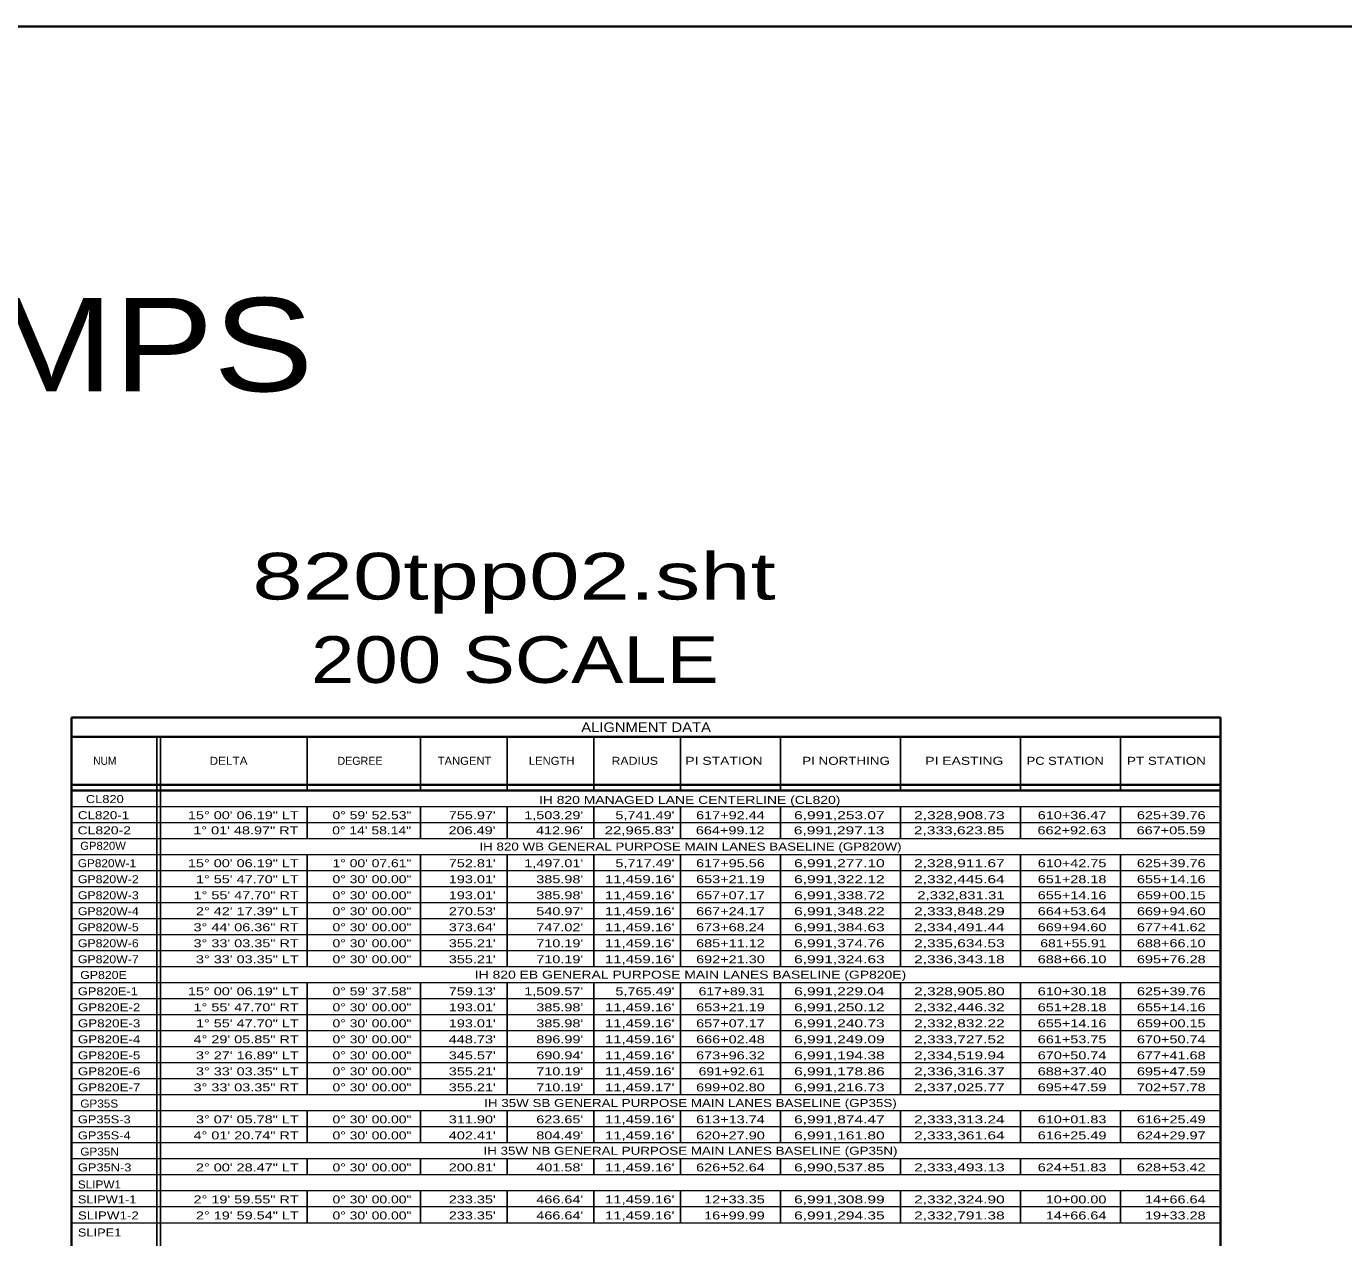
# Model space of a CAD drawing. Extents: x 1953053 to 1967065, y 7363860 to 7371201.
# Drawn here: x 1955866 to 1957841, y 7369385 to 7371201 of the extents above; entities that cross this region are included whole.
import ezdxf
from ezdxf.enums import TextEntityAlignment as Align

# ---------------------------------------------------------------- set-up
doc = ezdxf.new("R2010")
doc.units = 0
doc.header["$LTSCALE"] = 4.8
doc.layers.add('10', color=7, linetype='Continuous')
doc.layers.add('12', color=7, linetype='Continuous', lineweight=25)
doc.layers.add('62', color=7, linetype='Continuous', lineweight=35)

msp = doc.modelspace()

# ---------------------------------------------------------------- linework, layer by layer
at = {"layer": '12', "lineweight": 35}
for p, q in [((1957656.717, 7370164.879), (1955933.385, 7370164.879)), ((1955933.385, 7370164.879), (1955933.385, 7367607.746)), ((1957656.717, 7367607.746), (1957656.717, 7370164.879)), ((1955933.385, 7370136.079), (1957656.717, 7370136.079)), ((1955933.385, 7370064.079), (1957656.717, 7370064.079)), ((1955933.385, 7370055.746), (1957656.717, 7370055.746))]:
    msp.add_line(p, q, dxfattribs=at)
at = {"layer": '12'}
for p, q in [((1956061.23, 7370136.079), (1956061.23, 7367607.746)), ((1956066.717, 7370136.079), (1956066.717, 7367607.746)), ((1956286.717, 7370136.079), (1956286.717, 7370055.746)), ((1956456.717, 7370136.079), (1956456.717, 7370055.746)), ((1956586.717, 7370136.079), (1956586.717, 7370055.746)), ((1956716.717, 7370136.079), (1956716.717, 7370055.746)), ((1956846.717, 7370136.079), (1956846.717, 7370055.746)), ((1956996.717, 7370136.079), (1956996.717, 7370055.746)), ((1957176.717, 7370136.079), (1957176.717, 7370055.746)), ((1957356.717, 7370136.079), (1957356.717, 7370055.746)), ((1957506.717, 7370136.079), (1957506.717, 7370055.746)), ((1956061.23, 7370114.479), (1956061.23, 7369838.526)), ((1956286.717, 7370031.746), (1956286.717, 7369983.746)), ((1956456.717, 7370031.746), (1956456.717, 7369983.746)), ((1956586.717, 7370031.746), (1956586.717, 7369983.746)), ((1956716.717, 7370031.746), (1956716.717, 7369983.746)), ((1956846.717, 7370031.746), (1956846.717, 7369983.746)), ((1956996.717, 7370031.746), (1956996.717, 7369983.746)), ((1957176.717, 7370031.746), (1957176.717, 7369983.746)), ((1957356.717, 7370031.746), (1957356.717, 7369983.746)), ((1957506.717, 7370031.746), (1957506.717, 7369983.746)), ((1956286.717, 7369959.746), (1956286.717, 7369791.746)), ((1956456.717, 7369959.746), (1956456.717, 7369791.746)), ((1956586.717, 7369959.746), (1956586.717, 7369791.746)), ((1956716.717, 7369959.746), (1956716.717, 7369791.746)), ((1956846.717, 7369959.746), (1956846.717, 7369791.746)), ((1956996.717, 7369959.746), (1956996.717, 7369791.746)), ((1957176.717, 7369959.746), (1957176.717, 7369791.746)), ((1957356.717, 7369959.746), (1957356.717, 7369791.746)), ((1957506.717, 7369959.746), (1957506.717, 7369791.746)), ((1956286.717, 7369767.746), (1956286.717, 7369599.746)), ((1956456.717, 7369767.746), (1956456.717, 7369599.746)), ((1956586.717, 7369767.746), (1956586.717, 7369599.746)), ((1956716.717, 7369767.746), (1956716.717, 7369599.746)), ((1956846.717, 7369767.746), (1956846.717, 7369599.746)), ((1956996.717, 7369767.746), (1956996.717, 7369599.746)), ((1957176.717, 7369767.746), (1957176.717, 7369599.699)), ((1957356.717, 7369767.746), (1957356.717, 7369599.746)), ((1957506.717, 7369767.746), (1957506.717, 7369599.746)), ((1956286.717, 7369575.746), (1956286.717, 7369527.746)), ((1956456.717, 7369575.746), (1956456.717, 7369527.746)), ((1956586.717, 7369575.746), (1956586.717, 7369527.746)), ((1956716.717, 7369575.746), (1956716.717, 7369527.746)), ((1956846.717, 7369575.746), (1956846.717, 7369527.746)), ((1956996.717, 7369575.746), (1956996.717, 7369527.746)), ((1957176.717, 7369575.746), (1957176.717, 7369527.746)), ((1957356.717, 7369575.746), (1957356.717, 7369527.746)), ((1957506.717, 7369575.746), (1957506.717, 7369527.746)), ((1956286.717, 7369503.746), (1956286.717, 7369479.746)), ((1956456.717, 7369503.746), (1956456.717, 7369479.746)), ((1956586.717, 7369503.746), (1956586.717, 7369479.746)), ((1956716.717, 7369503.746), (1956716.717, 7369479.746)), ((1956846.717, 7369503.746), (1956846.717, 7369479.746)), ((1956996.717, 7369503.746), (1956996.717, 7369479.746)), ((1957176.717, 7369503.746), (1957176.717, 7369479.746)), ((1957356.717, 7369503.746), (1957356.717, 7369479.746)), ((1957506.717, 7369503.746), (1957506.717, 7369479.746)), ((1956286.717, 7369455.746), (1956286.717, 7369407.746)), ((1956456.717, 7369455.746), (1956456.717, 7369407.746)), ((1956586.717, 7369455.746), (1956586.717, 7369407.746)), ((1956716.717, 7369455.746), (1956716.717, 7369407.746)), ((1956846.717, 7369455.746), (1956846.717, 7369407.746)), ((1956996.717, 7369455.746), (1956996.717, 7369407.746)), ((1957176.717, 7369455.746), (1957176.717, 7369407.746)), ((1957356.717, 7369455.746), (1957356.717, 7369407.746)), ((1957506.717, 7369455.746), (1957506.717, 7369407.746))]:
    msp.add_line(p, q, dxfattribs=at)
at = {"layer": '12', "lineweight": 13}
for p, q in [((1955933.385, 7370031.746), (1957656.717, 7370031.746)), ((1955933.385, 7370007.746), (1957656.717, 7370007.746)), ((1955933.385, 7369983.746), (1957656.717, 7369983.746)), ((1955933.385, 7369959.746), (1957656.717, 7369959.746)), ((1955933.385, 7369935.746), (1957656.717, 7369935.746)), ((1955933.385, 7369911.746), (1957656.717, 7369911.746)), ((1955933.385, 7369887.746), (1957656.717, 7369887.746)), ((1955933.385, 7369863.746), (1957656.717, 7369863.746)), ((1955933.385, 7369839.746), (1957656.717, 7369839.746)), ((1955933.385, 7369815.746), (1957656.717, 7369815.746)), ((1955933.385, 7369791.746), (1957656.717, 7369791.746)), ((1955933.385, 7369767.746), (1957656.717, 7369767.746)), ((1955933.385, 7369743.746), (1957656.717, 7369743.746)), ((1955933.385, 7369719.746), (1957656.717, 7369719.746)), ((1955933.385, 7369695.746), (1957656.717, 7369695.746)), ((1955933.385, 7369671.746), (1957656.717, 7369671.746)), ((1955933.385, 7369647.746), (1957656.717, 7369647.746)), ((1955933.385, 7369623.746), (1957656.717, 7369623.746)), ((1955933.385, 7369599.746), (1957656.717, 7369599.746)), ((1955933.385, 7369575.746), (1957656.717, 7369575.746)), ((1955933.385, 7369551.746), (1957656.717, 7369551.746)), ((1955933.385, 7369527.746), (1957656.717, 7369527.746)), ((1955933.385, 7369503.746), (1957656.717, 7369503.746)), ((1955933.385, 7369479.746), (1957656.717, 7369479.746)), ((1955933.385, 7369455.746), (1957656.717, 7369455.746)), ((1955933.385, 7369431.746), (1957656.717, 7369431.746)), ((1955933.385, 7369407.746), (1957656.717, 7369407.746))]:
    msp.add_line(p, q, dxfattribs=at)
at = {"layer": '62'}
msp.add_lwpolyline([(1953052.784, 7371201.108), (1967065.314, 7371201.108), (1967065.314, 7363859.877), (1953052.784, 7363859.877)], close=True, dxfattribs=at)

# ---------------------------------------------------------------- texts
at = {"layer": '10'}
for s, width, p in [('CL820', 1.2, (1955955.056, 7370036.747)), ('CL820-1', 1.25, (1955943.006, 7370012.573)), ('CL820-2', 1.3, (1955942.614, 7369989.838)), ('GP820W', 1.05, (1955946.565, 7369966.718)), ('GP820W-1', 1.1, (1955943.006, 7369940.573)), ('GP820W-2', 1.15, (1955943.006, 7369916.573)), ('GP820W-3', 1.15, (1955943.006, 7369892.573)), ('GP820W-4', 1.15, (1955943.006, 7369868.573)), ('GP820W-5', 1.15, (1955943.006, 7369844.573)), ('GP820W-6', 1.15, (1955943.006, 7369820.573)), ('GP820W-7', 1.15, (1955943.006, 7369796.573)), ('GP820E', 1.15, (1955946.565, 7369773.083)), ('GP820E-1', 1.2, (1955943.006, 7369748.573)), ('GP820E-2', 1.25, (1955943.006, 7369724.573)), ('GP820E-3', 1.25, (1955943.006, 7369700.573)), ('GP820E-4', 1.25, (1955943.006, 7369676.573)), ('GP820E-5', 1.25, (1955943.006, 7369652.573)), ('GP820E-6', 1.25, (1955943.006, 7369628.573)), ('GP820E-7', 1.25, (1955943.006, 7369604.573)), ('GP35S', 1.1, (1955946.565, 7369580.275)), ('GP35S-3', 1.2, (1955943.006, 7369556.573)), ('GP35S-4', 1.2, (1955943.006, 7369532.573)), ('GP35N', 1.1, (1955946.565, 7369508.283)), ('GP35N-3', 1.2, (1955943.006, 7369484.573)), ('SLIPW1', 1.1, (1955943.006, 7369459.016)), ('SLIPW1-1', 1.2, (1955943.006, 7369436.573)), ('SLIPW1-2', 1.25, (1955943.006, 7369412.573)), ('SLIPE1', 1.2, (1955943.006, 7369387.016))]:
    msp.add_text(s, height=12, dxfattribs=dict(at, width=width)).set_placement(p)
for s, width, p in [('IH 820 MANAGED LANE CENTERLINE (CL820)', 1.3, (1956860.508, 7370035.509)), ('IH 820 WB GENERAL PURPOSE MAIN LANES BASELINE (GP820W)', 1.25, (1956861.718, 7369965.54)), ('IH 820 EB GENERAL PURPOSE MAIN LANES BASELINE (GP820E)', 1.3, (1956861.718, 7369773.54)), ('IH 35W SB GENERAL PURPOSE MAIN LANES BASELINE (GP35S)', 1.25, (1956861.717, 7369581.158)), ('IH 35W NB GENERAL PURPOSE MAIN LANES BASELINE (GP35N)', 1.25, (1956861.717, 7369509.54))]:
    msp.add_text(s, height=12, dxfattribs=dict(at, width=width)).set_placement(p, align=Align.CENTER)
for s, width, p in [('15° 00\' 06.19" LT', 1.35, (1956274.239, 7370012.573)), ('0° 59\' 52.53"', 1.3, (1956443.234, 7370012.573)), ("755.97'", 1.35, (1956569.644, 7370012.573)), ("1,503.29'", 1.35, (1956700.841, 7370012.573)), ("5,741.49'", 1.35, (1956837.61, 7370012.573)), ('617+92.44', 1.35, (1956973.154, 7370012.573)), ('6,991,253.07', 1.45, (1957152.919, 7370012.573)), ('2,328,908.73', 1.45, (1957332.919, 7370012.573)), ('610+36.47', 1.35, (1957485.497, 7370012.573)), ('625+39.76', 1.35, (1957634.229, 7370012.573)), ('1° 01\' 48.97" RT', 1.35, (1956273.847, 7369989.838)), ('0° 14\' 58.14"', 1.3, (1956442.842, 7369989.838)), ("206.49'", 1.35, (1956569.252, 7369989.838)), ("412.96'", 1.35, (1956700.449, 7369989.838)), ("22,965.83'", 1.4, (1956837.218, 7369989.838)), ('664+99.12', 1.35, (1956972.762, 7369989.838)), ('6,991,297.13', 1.45, (1957152.527, 7369989.838)), ('2,333,623.85', 1.45, (1957332.527, 7369989.838)), ('662+92.63', 1.35, (1957485.105, 7369989.838)), ('667+05.59', 1.35, (1957633.837, 7369989.838)), ('15° 00\' 06.19" LT', 1.35, (1956274.239, 7369940.573)), ('1° 00\' 07.61"', 1.3, (1956443.234, 7369940.573)), ("752.81'", 1.35, (1956569.644, 7369940.573)), ("1,497.01'", 1.35, (1956700.841, 7369940.573)), ("5,717.49'", 1.35, (1956837.61, 7369940.573)), ('617+95.56', 1.35, (1956973.154, 7369940.573)), ('6,991,277.10', 1.45, (1957152.919, 7369940.573)), ('2,328,911.67', 1.45, (1957332.919, 7369940.573)), ('610+42.75', 1.35, (1957485.497, 7369940.573)), ('625+39.76', 1.35, (1957634.229, 7369940.573)), ('1° 55\' 47.70" LT', 1.35, (1956274.239, 7369916.573)), ('0° 30\' 00.00"', 1.3, (1956443.234, 7369916.573)), ("193.01'", 1.35, (1956569.644, 7369916.573)), ("385.98'", 1.35, (1956700.841, 7369916.573)), ("11,459.16'", 1.4, (1956837.61, 7369916.573)), ('653+21.19', 1.35, (1956973.154, 7369916.573)), ('6,991,322.12', 1.45, (1957152.919, 7369916.573)), ('2,332,445.64', 1.45, (1957332.919, 7369916.573)), ('651+28.18', 1.35, (1957485.497, 7369916.573)), ('655+14.16', 1.35, (1957634.229, 7369916.573)), ('1° 55\' 47.70" RT', 1.35, (1956274.239, 7369892.573)), ('0° 30\' 00.00"', 1.3, (1956443.234, 7369892.573)), ("193.01'", 1.35, (1956569.644, 7369892.573)), ("385.98'", 1.35, (1956700.841, 7369892.573)), ("11,459.16'", 1.4, (1956837.61, 7369892.573)), ('657+07.17', 1.35, (1956973.154, 7369892.573)), ('6,991,338.72', 1.45, (1957152.919, 7369892.573)), ('2,332,831.31', 1.4, (1957332.919, 7369892.573)), ('655+14.16', 1.35, (1957485.497, 7369892.573)), ('659+00.15', 1.35, (1957634.229, 7369892.573)), ('2° 42\' 17.39" LT', 1.35, (1956274.239, 7369868.573)), ('0° 30\' 00.00"', 1.3, (1956443.234, 7369868.573)), ("270.53'", 1.35, (1956569.644, 7369868.573)), ("540.97'", 1.35, (1956700.841, 7369868.573)), ("11,459.16'", 1.4, (1956837.61, 7369868.573)), ('667+24.17', 1.35, (1956973.154, 7369868.573)), ('6,991,348.22', 1.45, (1957152.919, 7369868.573)), ('2,333,848.29', 1.45, (1957332.919, 7369868.573)), ('664+53.64', 1.35, (1957485.497, 7369868.573)), ('669+94.60', 1.35, (1957634.229, 7369868.573)), ('3° 44\' 06.36" RT', 1.35, (1956274.239, 7369844.573)), ('0° 30\' 00.00"', 1.3, (1956443.234, 7369844.573)), ("373.64'", 1.35, (1956569.644, 7369844.573)), ("747.02'", 1.35, (1956700.841, 7369844.573)), ("11,459.16'", 1.4, (1956837.61, 7369844.573)), ('673+68.24', 1.35, (1956973.154, 7369844.573)), ('6,991,384.63', 1.45, (1957152.919, 7369844.573)), ('2,334,491.44', 1.45, (1957332.919, 7369844.573)), ('669+94.60', 1.35, (1957485.497, 7369844.573)), ('677+41.62', 1.35, (1957634.229, 7369844.573)), ('3° 33\' 03.35" RT', 1.35, (1956274.239, 7369820.573)), ('0° 30\' 00.00"', 1.3, (1956443.234, 7369820.573)), ("355.21'", 1.35, (1956569.644, 7369820.573)), ("710.19'", 1.35, (1956700.841, 7369820.573)), ("11,459.16'", 1.4, (1956837.61, 7369820.573)), ('685+11.12', 1.35, (1956973.154, 7369820.573)), ('6,991,374.76', 1.45, (1957152.919, 7369820.573)), ('2,335,634.53', 1.45, (1957332.919, 7369820.573)), ('681+55.91', 1.3, (1957485.497, 7369820.573)), ('688+66.10', 1.35, (1957634.229, 7369820.573)), ('3° 33\' 03.35" LT', 1.35, (1956274.239, 7369796.573)), ('0° 30\' 00.00"', 1.3, (1956443.234, 7369796.573)), ("355.21'", 1.35, (1956569.644, 7369796.573)), ("710.19'", 1.35, (1956700.841, 7369796.573)), ("11,459.16'", 1.4, (1956837.61, 7369796.573)), ('692+21.30', 1.35, (1956973.154, 7369796.573)), ('6,991,324.63', 1.45, (1957152.919, 7369796.573)), ('2,336,343.18', 1.45, (1957332.919, 7369796.573)), ('688+66.10', 1.35, (1957485.497, 7369796.573)), ('695+76.28', 1.35, (1957634.229, 7369796.573)), ('15° 00\' 06.19" LT', 1.35, (1956274.239, 7369748.573)), ('0° 59\' 37.58"', 1.3, (1956443.234, 7369748.573)), ("759.13'", 1.35, (1956569.644, 7369748.573)), ("1,509.57'", 1.35, (1956700.841, 7369748.573)), ("5,765.49'", 1.35, (1956837.61, 7369748.573)), ('617+89.31', 1.3, (1956973.154, 7369748.573)), ('6,991,229.04', 1.45, (1957152.919, 7369748.573)), ('2,328,905.80', 1.45, (1957332.919, 7369748.573)), ('610+30.18', 1.35, (1957485.497, 7369748.573)), ('625+39.76', 1.35, (1957634.229, 7369748.573)), ('1° 55\' 47.70" RT', 1.35, (1956274.239, 7369724.573)), ('0° 30\' 00.00"', 1.3, (1956443.234, 7369724.573)), ("193.01'", 1.35, (1956569.644, 7369724.573)), ("385.98'", 1.35, (1956700.841, 7369724.573)), ("11,459.16'", 1.4, (1956837.61, 7369724.573)), ('653+21.19', 1.35, (1956973.154, 7369724.573)), ('6,991,250.12', 1.45, (1957152.919, 7369724.573)), ('2,332,446.32', 1.45, (1957332.919, 7369724.573)), ('651+28.18', 1.35, (1957485.497, 7369724.573)), ('655+14.16', 1.35, (1957634.229, 7369724.573)), ('1° 55\' 47.70" LT', 1.35, (1956274.239, 7369700.573)), ('0° 30\' 00.00"', 1.3, (1956443.234, 7369700.573)), ("193.01'", 1.35, (1956569.644, 7369700.573)), ("385.98'", 1.35, (1956700.841, 7369700.573)), ("11,459.16'", 1.4, (1956837.61, 7369700.573)), ('657+07.17', 1.35, (1956973.154, 7369700.573)), ('6,991,240.73', 1.45, (1957152.919, 7369700.573)), ('2,332,832.22', 1.45, (1957332.919, 7369700.573)), ('655+14.16', 1.35, (1957485.497, 7369700.573)), ('659+00.15', 1.35, (1957634.229, 7369700.573)), ('4° 29\' 05.85" RT', 1.35, (1956274.239, 7369676.573)), ('0° 30\' 00.00"', 1.3, (1956443.234, 7369676.573)), ("448.73'", 1.35, (1956569.644, 7369676.573)), ("896.99'", 1.35, (1956700.841, 7369676.573)), ("11,459.16'", 1.4, (1956837.61, 7369676.573)), ('666+02.48', 1.35, (1956973.154, 7369676.573)), ('6,991,249.09', 1.45, (1957152.919, 7369676.573)), ('2,333,727.52', 1.45, (1957332.919, 7369676.573)), ('661+53.75', 1.35, (1957485.497, 7369676.573)), ('670+50.74', 1.35, (1957634.229, 7369676.573)), ('3° 27\' 16.89" LT', 1.35, (1956274.239, 7369652.573)), ('0° 30\' 00.00"', 1.3, (1956443.234, 7369652.573)), ("345.57'", 1.35, (1956569.644, 7369652.573)), ("690.94'", 1.35, (1956700.841, 7369652.573)), ("11,459.16'", 1.4, (1956837.61, 7369652.573)), ('673+96.32', 1.35, (1956973.154, 7369652.573)), ('6,991,194.38', 1.45, (1957152.919, 7369652.573)), ('2,334,519.94', 1.45, (1957332.919, 7369652.573)), ('670+50.74', 1.35, (1957485.497, 7369652.573)), ('677+41.68', 1.35, (1957634.229, 7369652.573)), ('3° 33\' 03.35" LT', 1.35, (1956274.239, 7369628.573)), ('0° 30\' 00.00"', 1.3, (1956443.234, 7369628.573)), ("355.21'", 1.35, (1956569.644, 7369628.573)), ("710.19'", 1.35, (1956700.841, 7369628.573)), ("11,459.16'", 1.4, (1956837.61, 7369628.573)), ('691+92.61', 1.3, (1956973.154, 7369628.573)), ('6,991,178.86', 1.45, (1957152.919, 7369628.573)), ('2,336,316.37', 1.45, (1957332.919, 7369628.573)), ('688+37.40', 1.35, (1957485.497, 7369628.573)), ('695+47.59', 1.35, (1957634.229, 7369628.573)), ('3° 33\' 03.35" RT', 1.35, (1956274.239, 7369604.573)), ('0° 30\' 00.00"', 1.3, (1956443.234, 7369604.573)), ("355.21'", 1.35, (1956569.644, 7369604.573)), ("710.19'", 1.35, (1956700.841, 7369604.573)), ("11,459.17'", 1.4, (1956837.61, 7369604.573)), ('699+02.80', 1.35, (1956973.154, 7369604.573)), ('6,991,216.73', 1.45, (1957152.919, 7369604.573)), ('2,337,025.77', 1.45, (1957332.919, 7369604.573)), ('695+47.59', 1.35, (1957485.497, 7369604.573)), ('702+57.78', 1.35, (1957634.229, 7369604.573)), ('3° 07\' 05.78" LT', 1.35, (1956274.239, 7369556.573)), ('0° 30\' 00.00"', 1.3, (1956443.234, 7369556.573)), ("311.90'", 1.35, (1956569.644, 7369556.573)), ("623.65'", 1.35, (1956700.841, 7369556.573)), ("11,459.16'", 1.4, (1956837.61, 7369556.573)), ('613+13.74', 1.35, (1956973.154, 7369556.573)), ('6,991,874.47', 1.45, (1957152.919, 7369556.573)), ('2,333,313.24', 1.45, (1957332.919, 7369556.573)), ('610+01.83', 1.35, (1957485.497, 7369556.573)), ('616+25.49', 1.35, (1957634.229, 7369556.573)), ('4° 01\' 20.74" RT', 1.35, (1956274.239, 7369532.573)), ('0° 30\' 00.00"', 1.3, (1956443.234, 7369532.573)), ("402.41'", 1.35, (1956569.644, 7369532.573)), ("804.49'", 1.35, (1956700.841, 7369532.573)), ("11,459.16'", 1.4, (1956837.61, 7369532.573)), ('620+27.90', 1.35, (1956973.154, 7369532.573)), ('6,991,161.80', 1.45, (1957152.919, 7369532.573)), ('2,333,361.64', 1.45, (1957332.919, 7369532.573)), ('616+25.49', 1.35, (1957485.497, 7369532.573)), ('624+29.97', 1.35, (1957634.229, 7369532.573)), ('2° 00\' 28.47" LT', 1.35, (1956274.239, 7369484.573)), ('0° 30\' 00.00"', 1.3, (1956443.234, 7369484.573)), ("200.81'", 1.35, (1956569.644, 7369484.573)), ("401.58'", 1.35, (1956700.841, 7369484.573)), ("11,459.16'", 1.4, (1956837.61, 7369484.573)), ('626+52.64', 1.35, (1956973.154, 7369484.573)), ('6,990,537.85', 1.45, (1957152.919, 7369484.573)), ('2,333,493.13', 1.45, (1957332.919, 7369484.573)), ('624+51.83', 1.35, (1957485.497, 7369484.573)), ('628+53.42', 1.35, (1957634.229, 7369484.573)), ('2° 19\' 59.55" RT', 1.35, (1956274.239, 7369436.573)), ('0° 30\' 00.00"', 1.3, (1956443.234, 7369436.573)), ("233.35'", 1.35, (1956569.644, 7369436.573)), ("466.64'", 1.35, (1956700.841, 7369436.573)), ("11,459.16'", 1.4, (1956837.61, 7369436.573)), ('12+33.35', 1.35, (1956973.154, 7369436.573)), ('6,991,308.99', 1.45, (1957152.919, 7369436.573)), ('2,332,324.90', 1.45, (1957332.919, 7369436.573)), ('10+00.00', 1.35, (1957485.497, 7369436.573)), ('14+66.64', 1.35, (1957634.229, 7369436.573)), ('2° 19\' 59.54" LT', 1.35, (1956274.239, 7369412.573)), ('0° 30\' 00.00"', 1.3, (1956443.234, 7369412.573)), ("233.35'", 1.35, (1956569.644, 7369412.573)), ("466.64'", 1.35, (1956700.841, 7369412.573)), ("11,459.16'", 1.4, (1956837.61, 7369412.573)), ('16+99.99', 1.35, (1956973.154, 7369412.573)), ('6,991,294.35', 1.45, (1957152.919, 7369412.573)), ('2,332,791.38', 1.45, (1957332.919, 7369412.573)), ('14+66.64', 1.35, (1957485.497, 7369412.573)), ('19+33.28', 1.35, (1957634.229, 7369412.573))]:
    msp.add_text(s, height=12, dxfattribs=dict(at, width=width)).set_placement(p, align=Align.RIGHT)
at = {"layer": '12'}
for s, height, width, p in [('ALIGNMENT DATA', 14.4, 1.15, (1956795.158, 7370143.278)), ('NUM', 12, 0.95, (1955983.431, 7370094.075)), ('DELTA', 12, 1.1, (1956169.008, 7370094.078)), ('TANGENT', 12, 1.05, (1956522.905, 7370094.078)), ('LENGTH', 12, 1.05, (1956653.54, 7370094.078)), ('RADIUS', 12, 1.15, (1956778.15, 7370094.078)), ('PI STATION', 12, 1.3, (1956911.954, 7370094.078)), ('PI NORTHING', 12, 1.25, (1957095.029, 7370094.078)), ('PI EASTING', 12, 1.3, (1957272.421, 7370094.078)), ('PC STATION', 12, 1.2, (1957423.726, 7370094.078)), ('PT STATION', 12, 1.25, (1957575.497, 7370094.078))]:
    msp.add_text(s, height=height, dxfattribs=dict(at, width=width)).set_placement(p, align=Align.CENTER)
msp.add_text('DEGREE', height=12, dxfattribs=at).set_placement((1956366.094, 7370094.078), align=Align.CENTER)
at = {"layer": '62'}
for s, height, width, p in [('MAINLANES & RAMPS', 140, 1.2, (1955110.243, 7370654.085)), ('820tpp02.sht', 70, 1.45, (1956597.141, 7370341.878)), ('200 SCALE', 70, 1.25, (1956598.249, 7370216.878))]:
    msp.add_text(s, height=height, dxfattribs=dict(at, width=width)).set_placement(p, align=Align.CENTER)

doc.saveas('drawing.dxf')
